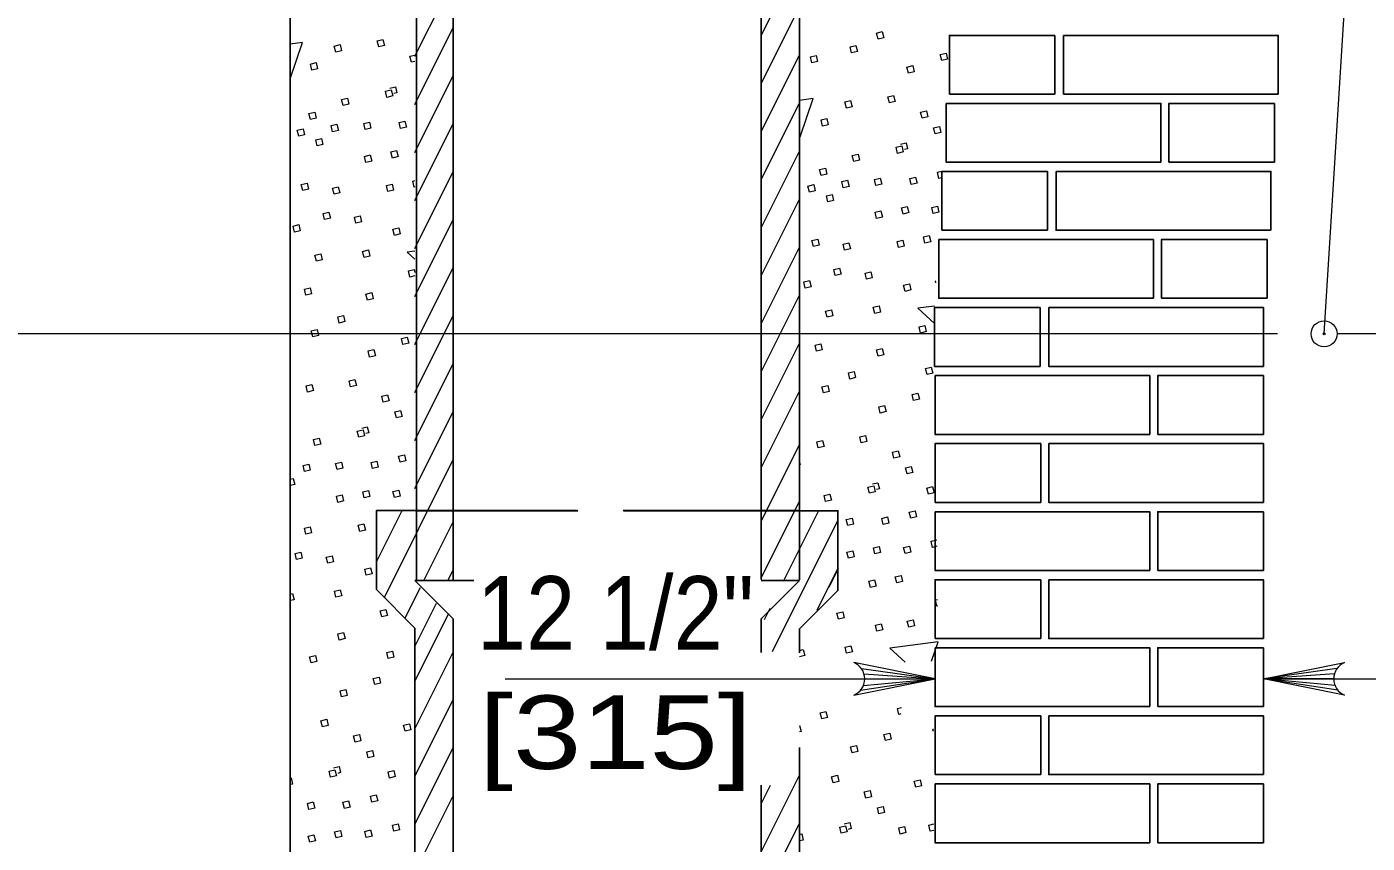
# Model space of a CAD drawing. Extents: x 750.7 to 784.7, y 860.1 to 882.1.
# Drawn here: x 760.016 to 762.937, y 866.601 to 868.379 of the extents above; entities that cross this region are included whole.
import ezdxf
from ezdxf.enums import TextEntityAlignment as Align

# ---------------------------------------------------------------- set-up
doc = ezdxf.new("R2010")
doc.units = 0
doc.header["$LTSCALE"] = 0.064
doc.linetypes.add('LONG_DASHED', pattern=[7.5, 6, -1.5])
doc.layers.add('1', color=7, linetype='Continuous', lineweight=13)

msp = doc.modelspace()

# ---------------------------------------------------------------- linework, layer by layer
at = {"layer": '1', "lineweight": 25}
for p, q in [((760.59067, 862.95208), (760.59067, 875.03808)), ((760.94567, 868.65992), (760.94567, 867.17508)), ((761.61633, 868.66), (761.61633, 867.17533)), ((760.86583, 868.63633), (760.86583, 867.17267)), ((761.7, 868.63867), (761.7, 867.174)), ((762.25667, 868.2325), (762.25667, 868.36058)), ((762.02658, 868.2325), (762.25667, 868.2325)), ((762.73517, 868.08425), (762.73517, 868.21225)), ((762.505, 868.08425), (762.73517, 868.08425)), ((762.2405, 867.936), (762.2405, 868.064)), ((762.01033, 867.936), (762.2405, 867.936)), ((762.71892, 867.78767), (762.71892, 867.91575)), ((762.48883, 867.78767), (762.71892, 867.78767)), ((762.22425, 867.63942), (762.22425, 867.7675)), ((761.99417, 867.63942), (762.22425, 867.63942)), ((762.71083, 867.49117), (762.71083, 867.61925)), ((762.48075, 867.49117), (762.71083, 867.49117)), ((762.22558, 867.34292), (762.22558, 867.471)), ((761.9955, 867.34292), (762.22558, 867.34292)), ((760.862, 867.325), (760.77825, 867.325)), ((760.862, 867.325), (760.77825, 867.325)), ((760.77825, 867.325), (760.77825, 867.15292)), ((761.78492, 867.32467), (761.70125, 867.32467)), ((761.78367, 867.325), (761.78367, 867.15133)), ((762.71083, 867.19467), (762.71083, 867.32267)), ((760.862, 867.17267), (760.94567, 867.089)), ((760.99083, 867.17267), (760.862, 867.17267)), ((760.98517, 867.17267), (760.86583, 867.17267)), ((761.7, 867.17267), (761.61633, 867.089)), ((761.7, 867.17267), (761.61633, 867.17267)), ((761.7, 867.17267), (761.61633, 867.17267)), ((762.22558, 867.04633), (762.22558, 867.17442)), ((762.48075, 867.19467), (762.71083, 867.19467)), ((760.77833, 867.15292), (760.862, 867.06925)), ((761.78367, 867.15133), (761.7, 867.06767)), ((760.94567, 867.089), (760.94567, 865.63483)), ((761.61633, 867.089), (761.61633, 867.01625)), ((760.862, 867.06925), (760.862, 865.6345)), ((761.7, 867.06767), (761.7, 867.01492)), ((761.9955, 867.04633), (762.22558, 867.04633)), ((762.71083, 866.89808), (762.71083, 867.02617)), ((762.22558, 866.74983), (762.22558, 866.87792)), ((762.48075, 866.89808), (762.71083, 866.89808)), ((761.7, 866.80892), (761.7, 865.6345)), ((761.9955, 866.74983), (762.22558, 866.74983)), ((762.71083, 866.60158), (762.71083, 866.72967)), ((761.61633, 866.72725), (761.61633, 865.63483)), ((762.48075, 866.60158), (762.71083, 866.60158))]:
    msp.add_line(p, q, dxfattribs=at)
at = {"layer": '1'}
for p, q in [((762.84308, 867.71025), (762.92467, 869.00808)), ((761.61633, 868.35967), (761.7, 868.527)), ((760.862, 868.31492), (760.94567, 868.48225)), ((761.61633, 868.255), (761.7, 868.42242)), ((760.862, 868.21025), (760.94567, 868.37767)), ((760.617, 868.34483), (760.59067, 868.34133)), ((760.59067, 868.26583), (760.617, 868.34483)), ((761.61633, 868.15042), (761.7, 868.31783)), ((760.8075, 868.24575), (760.81958, 868.24858)), ((760.862, 868.10567), (760.94567, 868.27308)), ((761.72967, 868.22292), (761.7, 868.21892)), ((761.61633, 868.04583), (761.7, 868.21325)), ((760.862, 868.00108), (760.94567, 868.1685)), ((761.61633, 867.94125), (761.7, 868.10858)), ((761.92017, 868.12375), (761.93225, 868.12658)), ((760.862, 867.8965), (760.94567, 868.06383)), ((761.61633, 867.83658), (761.7, 868.004)), ((760.862, 867.79192), (760.94567, 867.95925)), ((761.61633, 867.732), (761.7, 867.89942)), ((760.86042, 867.85025), (760.862, 867.84392)), ((760.862, 867.68725), (760.94567, 867.85467)), ((761.61633, 867.62742), (761.7, 867.79483)), ((760.862, 867.58267), (760.94567, 867.75008)), ((762.7415, 867.71042), (758.81575, 867.71033)), ((764.87633, 867.71042), (762.87142, 867.71042)), ((761.61633, 867.52283), (761.7, 867.69017)), ((760.862, 867.47808), (760.94567, 867.64542)), ((761.61633, 867.41817), (761.7, 867.58558)), ((760.862, 867.37342), (760.94567, 867.54083)), ((760.74617, 867.50508), (760.75825, 867.508)), ((761.61758, 867.30383), (761.70125, 867.47117)), ((760.79625, 867.13733), (760.94567, 867.43625)), ((760.59067, 867.39392), (760.59708, 867.39542)), ((761.85883, 867.38317), (761.87092, 867.386)), ((761.61633, 867.17808), (761.7, 867.3455)), ((760.77858, 867.21325), (760.8345, 867.325)), ((761.66508, 867.17108), (761.74208, 867.325)), ((760.88158, 867.17267), (760.94567, 867.30075)), ((761.641, 867.01817), (761.78367, 867.30367)), ((760.93433, 867.1735), (760.94567, 867.19617)), ((761.73825, 867.10808), (761.78367, 867.19908)), ((761.76508, 867.15908), (761.78492, 867.19867)), ((760.59067, 867.14308), (760.59567, 867.14433)), ((760.84092, 867.09133), (760.87408, 867.15767)), ((760.86208, 867.02908), (760.90925, 867.12342)), ((761.62358, 867.08792), (761.636, 867.11275)), ((760.862, 866.95292), (760.93617, 867.10142)), ((761.69975, 867.062), (761.7, 867.06258)), ((761.7, 867.02033), (761.70833, 867.02233)), ((761.98783, 866.99675), (762.00192, 867.03892)), ((760.862, 866.84942), (760.945, 867.01542)), ((761.83508, 866.98092), (761.99542, 866.9585)), ((761.8405, 866.96983), (761.99542, 866.9585)), ((762.87117, 866.98092), (762.71083, 866.9585)), ((762.86575, 866.96983), (762.71083, 866.9585)), ((761.0585, 866.9585), (761.99542, 866.9585)), ((761.83325, 866.93375), (761.99542, 866.9585)), ((761.83933, 866.94408), (761.99542, 866.9585)), ((761.84217, 866.9585), (761.99542, 866.9585)), ((762.71083, 866.9585), (764.06567, 866.9585)), ((762.86408, 866.9585), (762.71083, 866.9585)), ((762.86692, 866.94408), (762.71083, 866.9585)), ((762.87308, 866.93375), (762.71083, 866.9585)), ((760.862, 866.74583), (760.945, 866.91183)), ((761.7, 866.85717), (761.70033, 866.85725)), ((760.862, 866.64125), (760.94567, 866.80867)), ((760.68483, 866.7645), (760.697, 866.76742)), ((760.59067, 866.74225), (760.59233, 866.74258)), ((761.61633, 866.58133), (761.7, 866.74875)), ((760.862, 866.53667), (760.94567, 866.704)), ((761.61633, 866.686), (761.63667, 866.72667)), ((761.61633, 866.47675), (761.7, 866.64417)), ((761.7975, 866.64258), (761.80967, 866.64542)), ((761.7, 866.61942), (761.705, 866.62067))]:
    msp.add_line(p, q, dxfattribs=at)
at = {"layer": '1', "linetype": 'LONG_DASHED', "lineweight": 25}
for p, q in [((761.7, 867.325), (760.862, 867.325)), ((761.70125, 867.32467), (760.86317, 867.32467))]:
    msp.add_line(p, q, dxfattribs=at)
at = {"layer": '1'}
for points in [[(761.8805, 868.36867), (761.88367, 868.35542), (761.87117, 868.35242), (761.86792, 868.36567)], [(760.69892, 868.34033), (760.70208, 868.32708), (760.68958, 868.32408), (760.68633, 868.33733)], [(760.79258, 868.35158), (760.79583, 868.33833), (760.78325, 868.33533), (760.78008, 868.34858)], [(761.823, 868.33842), (761.82617, 868.32517), (761.81358, 868.32217), (761.81042, 868.33542)], [(761.73642, 868.317), (761.73967, 868.30375), (761.72708, 868.30075), (761.72392, 868.314)], [(762.01933, 868.32175), (762.02258, 868.3085), (762.01, 868.3055), (762.00683, 868.31875)], [(760.64692, 868.30117), (760.65008, 868.28792), (760.6375, 868.28492), (760.63433, 868.29817)], [(761.94675, 868.29458), (761.95, 868.28133), (761.93742, 868.27833), (761.93417, 868.29158)], [(760.715, 868.22375), (760.71817, 868.21058), (760.70558, 868.20758), (760.70242, 868.22075)], [(760.8105, 868.24175), (760.81367, 868.2285), (760.80117, 868.2255), (760.79792, 868.23875)], [(761.81158, 868.21842), (761.81475, 868.20517), (761.80225, 868.20217), (761.799, 868.21542)], [(761.90525, 868.22958), (761.9085, 868.21633), (761.89592, 868.21333), (761.89275, 868.22658)], [(760.64392, 868.19342), (760.64708, 868.18017), (760.6345, 868.17717), (760.63133, 868.19042)], [(761.9765, 868.19625), (761.97967, 868.183), (761.96717, 868.18), (761.96392, 868.19325)], [(760.69225, 868.16683), (760.6955, 868.15358), (760.68292, 868.15058), (760.67975, 868.16383)], [(760.76325, 868.1715), (760.76642, 868.15825), (760.75392, 868.15525), (760.75067, 868.1685)], [(760.84042, 868.17375), (760.84358, 868.16058), (760.831, 868.15758), (760.82783, 868.17083)], [(761.75958, 868.17917), (761.76275, 868.16592), (761.75017, 868.16292), (761.747, 868.17617)], [(762.005, 868.16192), (762.00817, 868.14867), (761.99567, 868.14567), (761.99242, 868.15892)], [(760.61842, 868.15725), (760.62158, 868.144), (760.60908, 868.14108), (760.60583, 868.15425)], [(760.65842, 868.136), (760.66167, 868.12275), (760.64908, 868.11975), (760.64592, 868.133)], [(760.82233, 868.10958), (760.8255, 868.09633), (760.813, 868.09333), (760.80975, 868.10658)], [(761.82767, 868.10183), (761.83083, 868.08858), (761.81825, 868.08558), (761.81508, 868.09883)], [(761.92317, 868.11975), (761.92633, 868.1065), (761.91383, 868.1035), (761.91058, 868.11675)], [(760.76483, 868.09992), (760.768, 868.08667), (760.75542, 868.08367), (760.75225, 868.09692)], [(761.75658, 868.07142), (761.75975, 868.05817), (761.74717, 868.05517), (761.744, 868.06842)], [(761.80492, 868.04483), (761.80817, 868.03158), (761.79558, 868.02858), (761.79242, 868.04183)], [(761.87592, 868.0495), (761.87917, 868.03625), (761.86658, 868.03325), (761.86333, 868.0465)], [(761.95308, 868.05183), (761.95625, 868.03858), (761.94367, 868.03558), (761.9405, 868.04883)], [(760.62708, 868.03875), (760.63033, 868.0255), (760.61775, 868.0225), (760.61458, 868.03575)], [(760.69525, 868.03067), (760.69842, 868.01742), (760.68583, 868.01442), (760.68267, 868.02767)], [(760.8125, 868.03667), (760.81567, 868.02342), (760.80317, 868.02042), (760.79992, 868.03367)], [(761.73108, 868.03533), (761.73425, 868.02208), (761.72175, 868.01908), (761.7185, 868.03233)], [(761.77108, 868.014), (761.77433, 868.00083), (761.76175, 867.99783), (761.75858, 868.01108)], [(761.935, 867.98758), (761.93817, 867.97433), (761.92567, 867.97133), (761.92242, 867.98458)], [(762.00075, 867.9885), (762.00392, 867.97525), (761.99142, 867.97233), (761.98817, 867.9855)], [(760.67475, 867.97542), (760.678, 867.96217), (760.66542, 867.95917), (760.66225, 867.97242)], [(760.74292, 867.96742), (760.74608, 867.95417), (760.73358, 867.95117), (760.73033, 867.96442)], [(761.8775, 867.97792), (761.88067, 867.96475), (761.86808, 867.96175), (761.86492, 867.975)], [(760.60925, 867.94817), (760.61242, 867.93492), (760.59992, 867.93192), (760.59667, 867.94517)], [(760.82692, 867.94108), (760.83008, 867.92783), (760.81758, 867.92483), (760.81433, 867.93808)], [(761.73975, 867.91675), (761.743, 867.9035), (761.73042, 867.9005), (761.72725, 867.91375)], [(761.80792, 867.90875), (761.81108, 867.8955), (761.7985, 867.8925), (761.79533, 867.90575)], [(761.92517, 867.91467), (761.92833, 867.90142), (761.91583, 867.89842), (761.91258, 867.91167)], [(761.98267, 867.92433), (761.98592, 867.91108), (761.97333, 867.90808), (761.97017, 867.92133)], [(760.65692, 867.88492), (760.66017, 867.87167), (760.64758, 867.86867), (760.64442, 867.88192)], [(760.76075, 867.893), (760.764, 867.87975), (760.75142, 867.87675), (760.74825, 867.89)], [(761.7875, 867.8535), (761.79067, 867.84025), (761.77808, 867.83725), (761.77492, 867.8505)], [(761.85558, 867.84542), (761.85875, 867.83217), (761.84625, 867.82917), (761.843, 867.84242)], [(760.63392, 867.81075), (760.63708, 867.7975), (760.62458, 867.7945), (760.62133, 867.80775)], [(761.72192, 867.82625), (761.72517, 867.813), (761.71258, 867.81), (761.70933, 867.82325)], [(761.93958, 867.81908), (761.94275, 867.80583), (761.93025, 867.80283), (761.927, 867.81608)], [(760.76792, 867.8), (760.77117, 867.78675), (760.75858, 867.78375), (760.75542, 867.797)], [(761.76958, 867.76292), (761.77283, 867.74967), (761.76025, 867.74667), (761.75708, 867.75992)], [(761.8735, 867.77108), (761.87667, 867.75783), (761.86408, 867.75483), (761.86092, 867.76808)], [(760.7065, 867.75008), (760.70967, 867.73683), (760.69717, 867.73383), (760.69392, 867.74708)], [(761.97308, 867.72825), (761.97633, 867.715), (761.96375, 867.712), (761.96058, 867.72525)], [(760.649, 867.71975), (760.65217, 867.7065), (760.63967, 867.7035), (760.63642, 867.71675)], [(760.84533, 867.70308), (760.84858, 867.68983), (760.836, 867.68683), (760.83283, 867.70008)], [(760.77275, 867.67592), (760.776, 867.66267), (760.76342, 867.65975), (760.76025, 867.67292)], [(761.74658, 867.68883), (761.74983, 867.67558), (761.73725, 867.67258), (761.734, 867.68583)], [(761.88058, 867.67808), (761.88383, 867.66483), (761.87125, 867.66183), (761.86808, 867.67508)], [(761.98725, 867.63775), (761.99042, 867.6245), (761.97792, 867.62158), (761.97467, 867.63475)], [(760.73125, 867.611), (760.7345, 867.59775), (760.72192, 867.59475), (760.71875, 867.608)], [(761.81917, 867.62808), (761.82233, 867.61483), (761.80983, 867.61183), (761.80658, 867.62508)], [(760.63758, 867.59975), (760.64083, 867.5865), (760.62825, 867.5835), (760.625, 867.59675)], [(760.8025, 867.57767), (760.80575, 867.56442), (760.79317, 867.56142), (760.78992, 867.57467)], [(761.76167, 867.59783), (761.76483, 867.58458), (761.75233, 867.58158), (761.74908, 867.59483)], [(761.958, 867.58117), (761.96125, 867.56792), (761.94867, 867.56492), (761.9455, 867.57817)], [(761.88542, 867.554), (761.88867, 867.54075), (761.87608, 867.53775), (761.87292, 867.551)], [(760.831, 867.54325), (760.83417, 867.53008), (760.82167, 867.52708), (760.81842, 867.54033)], [(760.74917, 867.50117), (760.75233, 867.48792), (760.73983, 867.48492), (760.73658, 867.49817)], [(761.84392, 867.489), (761.84717, 867.47575), (761.83458, 867.47275), (761.83142, 867.486)], [(760.65367, 867.48317), (760.65683, 867.46992), (760.64425, 867.467), (760.64108, 867.48017)], [(761.75025, 867.47775), (761.7535, 867.46458), (761.74092, 867.46158), (761.73775, 867.47483)], [(760.70192, 867.43092), (760.70517, 867.41767), (760.69258, 867.41467), (760.68942, 867.42792)], [(760.77908, 867.43317), (760.78225, 867.42), (760.76975, 867.417), (760.7665, 867.43017)], [(760.83917, 867.44658), (760.84242, 867.43333), (760.82983, 867.43033), (760.82667, 867.44358)], [(761.91517, 867.45567), (761.91842, 867.44242), (761.90583, 867.43942), (761.90267, 867.45267)], [(760.63092, 867.42625), (760.63417, 867.413), (760.62158, 867.41), (760.61842, 867.42325)], [(761.94367, 867.42133), (761.94692, 867.40808), (761.93433, 867.40508), (761.93108, 867.41833)], [(761.86183, 867.37917), (761.865, 867.36592), (761.8525, 867.36292), (761.84925, 867.37617)], [(761.99017, 867.37733), (761.99333, 867.36408), (761.98083, 867.36117), (761.97758, 867.37433)], [(760.7035, 867.35933), (760.70667, 867.34608), (760.69408, 867.34308), (760.69092, 867.35633)], [(760.761, 867.369), (760.76417, 867.35575), (760.75167, 867.35275), (760.74842, 867.366)], [(760.82675, 867.36992), (760.83, 867.35667), (760.81742, 867.35367), (760.81417, 867.36692)], [(761.76633, 867.36125), (761.7695, 867.348), (761.757, 867.345), (761.75375, 867.35825)], [(761.95183, 867.32458), (761.95508, 867.31133), (761.9425, 867.30833), (761.93933, 867.32158)], [(760.63392, 867.29008), (760.63708, 867.27683), (760.62458, 867.27383), (760.62133, 867.28708)], [(760.75117, 867.29608), (760.75433, 867.28283), (760.74183, 867.27983), (760.73858, 867.29308)], [(761.81458, 867.30892), (761.81783, 867.29567), (761.80525, 867.29267), (761.80208, 867.30592)], [(761.89175, 867.31125), (761.89492, 867.298), (761.88242, 867.295), (761.87917, 867.30825)], [(760.6135, 867.23483), (760.61667, 867.22158), (760.60408, 867.21858), (760.60092, 867.23183)], [(760.68158, 867.22683), (760.68483, 867.21358), (760.67225, 867.21058), (760.669, 867.22383)], [(761.81617, 867.23733), (761.81933, 867.22417), (761.80683, 867.22117), (761.80358, 867.23442)], [(761.87367, 867.247), (761.87683, 867.23375), (761.86433, 867.23075), (761.86108, 867.244)], [(761.93942, 867.24792), (761.94267, 867.23467), (761.93008, 867.23167), (761.92692, 867.24492)], [(760.76558, 867.2005), (760.76875, 867.18725), (760.75625, 867.18425), (760.753, 867.1975)], [(761.86383, 867.17408), (761.86708, 867.16083), (761.8545, 867.15783), (761.85125, 867.17108)], [(761.92133, 867.18375), (761.92458, 867.1705), (761.912, 867.1675), (761.90883, 867.18075)], [(760.6995, 867.15242), (760.70267, 867.13917), (760.69008, 867.13617), (760.68692, 867.14942)], [(760.79908, 867.10958), (760.80233, 867.09642), (760.78975, 867.09342), (760.78658, 867.10667)], [(761.79425, 867.10483), (761.7975, 867.09158), (761.78492, 867.08858), (761.78167, 867.10183)], [(761.94742, 867.0875), (761.95058, 867.07433), (761.93808, 867.07133), (761.93483, 867.08458)], [(760.70667, 867.05942), (760.70983, 867.04617), (760.69725, 867.04317), (760.69408, 867.05642)], [(761.87825, 867.0785), (761.8815, 867.06525), (761.86892, 867.06225), (761.86575, 867.0755)], [(761.81217, 867.0305), (761.81533, 867.01725), (761.80275, 867.01425), (761.79958, 867.0275)], [(760.64517, 867.0095), (760.64833, 866.99625), (760.63583, 866.99325), (760.63258, 867.0065)], [(760.81325, 867.01917), (760.81642, 867.00592), (760.80392, 867.00292), (760.80067, 867.01617)], [(760.78408, 866.9625), (760.78725, 866.94925), (760.77467, 866.94625), (760.7715, 866.9595)], [(760.71142, 866.93533), (760.71467, 866.92208), (760.70208, 866.91908), (760.69892, 866.93233)], [(761.75783, 866.8875), (761.761, 866.87425), (761.7485, 866.87125), (761.74525, 866.8845)], [(760.66992, 866.87042), (760.67317, 866.85717), (760.66058, 866.85417), (760.65742, 866.86742)], [(760.85017, 866.86067), (760.85333, 866.84742), (760.84083, 866.84442), (760.83758, 866.85767)], [(760.74117, 866.83708), (760.74442, 866.82383), (760.73183, 866.82083), (760.72867, 866.83408)], [(761.89675, 866.84058), (761.89992, 866.82733), (761.88733, 866.82433), (761.88417, 866.83758)], [(760.76967, 866.80267), (760.77292, 866.78942), (760.76033, 866.7865), (760.75717, 866.79967)], [(761.82408, 866.81342), (761.82733, 866.80017), (761.81475, 866.79717), (761.81158, 866.81042)], [(760.68783, 866.7605), (760.691, 866.74733), (760.6785, 866.74433), (760.67525, 866.75758)], [(760.81617, 866.75875), (760.81933, 866.7455), (760.80683, 866.7425), (760.80358, 866.75575)], [(761.78267, 866.74842), (761.78583, 866.73517), (761.77325, 866.73217), (761.77008, 866.74542)], [(761.96283, 866.73867), (761.96608, 866.72542), (761.9535, 866.72242), (761.95025, 866.73567)], [(760.77792, 866.706), (760.78108, 866.69275), (760.7685, 866.68975), (760.76533, 866.703)], [(761.85383, 866.71508), (761.85708, 866.70183), (761.8445, 866.69883), (761.84133, 866.71208)], [(760.64058, 866.69033), (760.64383, 866.67708), (760.63125, 866.67408), (760.62808, 866.68733)], [(760.71775, 866.69258), (760.72092, 866.67933), (760.70842, 866.67633), (760.70517, 866.68958)], [(761.88233, 866.68075), (761.88558, 866.6675), (761.873, 866.6645), (761.86983, 866.67775)], [(760.82558, 866.64267), (760.82875, 866.6295), (760.81617, 866.6265), (760.813, 866.63975)], [(760.64217, 866.61875), (760.64533, 866.6055), (760.63283, 866.6025), (760.62958, 866.61575)], [(760.69967, 866.62842), (760.70292, 866.61517), (760.69033, 866.61217), (760.68717, 866.62542)], [(760.76542, 866.62933), (760.76867, 866.61608), (760.75608, 866.61308), (760.75292, 866.62633)], [(761.8005, 866.63858), (761.80375, 866.62533), (761.79117, 866.62233), (761.788, 866.63558)], [(761.92883, 866.63675), (761.932, 866.6235), (761.9195, 866.6205), (761.91625, 866.63375)]]:
    msp.add_lwpolyline(points, close=True, dxfattribs=at)
at = {"layer": '1', "lineweight": 25}
for points in [[(762.02658, 868.2325), (762.02658, 868.36058), (762.25667, 868.36058)], [(762.74325, 868.2325), (762.74325, 868.36058), (762.27558, 868.36058)], [(762.74325, 868.2325), (762.27558, 868.2325), (762.27558, 868.36058)], [(762.4875, 868.08425), (762.4875, 868.21225), (762.01975, 868.21225)], [(762.4875, 868.08425), (762.01975, 868.08425), (762.01975, 868.21225)], [(762.505, 868.08425), (762.505, 868.21225), (762.73517, 868.21225)], [(762.01033, 867.936), (762.01033, 868.064), (762.2405, 868.064)], [(762.72708, 867.936), (762.72708, 868.064), (762.25933, 868.064)], [(762.72708, 867.936), (762.25933, 867.936), (762.25933, 868.064)], [(762.47125, 867.78767), (762.47125, 867.91575), (762.00358, 867.91575)], [(762.47125, 867.78767), (762.00358, 867.78767), (762.00358, 867.91575)], [(762.48883, 867.78767), (762.48883, 867.91575), (762.71892, 867.91575)], [(761.99417, 867.63942), (761.99417, 867.7675), (762.22425, 867.7675)], [(762.71083, 867.63942), (762.71083, 867.7675), (762.24317, 867.7675)], [(762.71083, 867.63942), (762.24317, 867.63942), (762.24317, 867.7675)], [(762.46308, 867.49117), (762.46308, 867.61925), (761.99542, 867.61925)], [(762.46308, 867.49117), (761.99542, 867.49117), (761.99542, 867.61925)], [(762.48075, 867.49117), (762.48075, 867.61925), (762.71083, 867.61925)], [(761.9955, 867.34292), (761.9955, 867.471), (762.22558, 867.471)], [(762.71083, 867.34292), (762.71083, 867.471), (762.24317, 867.471)], [(762.71083, 867.34292), (762.24317, 867.34292), (762.24317, 867.471)], [(762.46308, 867.19467), (762.46308, 867.32275), (761.99542, 867.32267)], [(762.46308, 867.19467), (761.99542, 867.19467), (761.99542, 867.32267)], [(762.48075, 867.19467), (762.48075, 867.32267), (762.71083, 867.32267)], [(761.9955, 867.04633), (761.9955, 867.17442), (762.22558, 867.17442)], [(762.71083, 867.04633), (762.71083, 867.17442), (762.24317, 867.17442)], [(762.71083, 867.04633), (762.24317, 867.04633), (762.24317, 867.17442)], [(762.46308, 866.89808), (762.46308, 867.02617), (761.99542, 867.02617)], [(762.46308, 866.89808), (761.99542, 866.89808), (761.99542, 867.02617)], [(762.48075, 866.89808), (762.48075, 867.02617), (762.71083, 867.02617)], [(761.9955, 866.74983), (761.9955, 866.87792), (762.22558, 866.87792)], [(762.71083, 866.74983), (762.71083, 866.87792), (762.24317, 866.87792)], [(762.71083, 866.74983), (762.24317, 866.74983), (762.24317, 866.87792)], [(762.46308, 866.60158), (762.46308, 866.72967), (761.99542, 866.72967)], [(762.46308, 866.60158), (761.99542, 866.60158), (761.99542, 866.72967)], [(762.48075, 866.60158), (762.48075, 866.72967), (762.71083, 866.72967)]]:
    msp.add_lwpolyline(points, dxfattribs=at)
at = {"layer": '1'}
for points in [[(760.862, 868.30375), (760.8545, 868.302), (760.85125, 868.31525), (760.862, 868.31775)], [(760.81958, 868.24858), (760.82283, 868.23533), (760.8165, 868.23383)], [(761.7, 868.14075), (761.70175, 868.13917), (761.72967, 868.22292)], [(761.93225, 868.12658), (761.9355, 868.11342), (761.92917, 868.11183)], [(760.862, 868.03033), (760.86067, 868.03008), (760.8575, 868.04325), (760.862, 868.04433)], [(762.00975, 868.05033), (762.00383, 868.049), (762.00067, 868.06225), (762.0105, 868.06458)], [(760.862, 867.89017), (760.84525, 867.88792), (760.862, 867.87292)], [(760.862, 867.83658), (760.85108, 867.834), (760.84792, 867.84725), (760.86042, 867.85025)], [(761.99708, 867.82133), (761.99617, 867.82517), (761.99733, 867.82542)], [(761.99433, 867.77083), (761.95792, 867.76592), (761.9945, 867.73308)], [(760.75825, 867.508), (760.7615, 867.49475), (760.75517, 867.49317)], [(761.7, 867.43117), (761.70142, 867.42533), (761.7, 867.425)], [(760.59708, 867.39542), (760.60033, 867.38217), (760.59067, 867.37983)], [(761.87092, 867.386), (761.87417, 867.37275), (761.86783, 867.37125)], [(761.99967, 867.24733), (761.99017, 867.24508), (761.987, 867.25833), (761.9995, 867.26133)], [(760.59567, 867.14433), (760.59883, 867.13108), (760.59067, 867.12908)], [(762.00108, 867.11767), (761.9995, 867.11725), (761.99633, 867.1305), (762.00092, 867.13167)], [(761.70833, 867.02233), (761.7115, 867.00908), (761.7, 867.00633)], [(762.00192, 867.03942), (761.89658, 867.02533), (761.9305, 866.99492)], [(761.81833, 866.92308), (761.99542, 866.9585), (761.81833, 866.99392)], [(762.88792, 866.92308), (762.71083, 866.9585), (762.88792, 866.99392)], [(760.59067, 866.96675), (760.59083, 866.96592), (760.59067, 866.96592)], [(761.92092, 866.882), (761.91658, 866.88092), (761.91333, 866.89417), (761.92208, 866.89625)], [(761.70033, 866.85725), (761.7035, 866.844), (761.7, 866.84317)], [(761.99225, 866.8435), (761.99092, 866.84883), (761.99225, 866.84917)], [(760.697, 866.76742), (760.70017, 866.75417), (760.69383, 866.75258)], [(760.59233, 866.74258), (760.5955, 866.72933), (760.59067, 866.72825)], [(761.80967, 866.64542), (761.81283, 866.63217), (761.8065, 866.63067)], [(761.99267, 866.62833), (761.985, 866.6265), (761.98183, 866.63975), (761.99267, 866.64233)], [(761.705, 866.62067), (761.70817, 866.60742), (761.7, 866.60542)]]:
    msp.add_lwpolyline(points, dxfattribs=at)
for radius in [0.02833, 0.00189]:
    msp.add_circle((762.84311, 867.71023), radius, dxfattribs=at)
for centre, start, end in [((761.80404, 866.95855), 292.08605, 67.91218), ((762.90222, 866.95855), 112.08782, 247.91395)]:
    msp.add_arc(centre, 0.03822, start, end, dxfattribs=at)

# ---------------------------------------------------------------- texts
for s, width, p in [('12 1/2"', 0.9, (761.29908, 867.02233)), ('[315]', 1.25, (761.29904, 866.76233))]:
    msp.add_text(s, height=0.16, dxfattribs=dict(at, width=width)).set_placement(p, align=Align.CENTER)

doc.saveas('drawing.dxf')
